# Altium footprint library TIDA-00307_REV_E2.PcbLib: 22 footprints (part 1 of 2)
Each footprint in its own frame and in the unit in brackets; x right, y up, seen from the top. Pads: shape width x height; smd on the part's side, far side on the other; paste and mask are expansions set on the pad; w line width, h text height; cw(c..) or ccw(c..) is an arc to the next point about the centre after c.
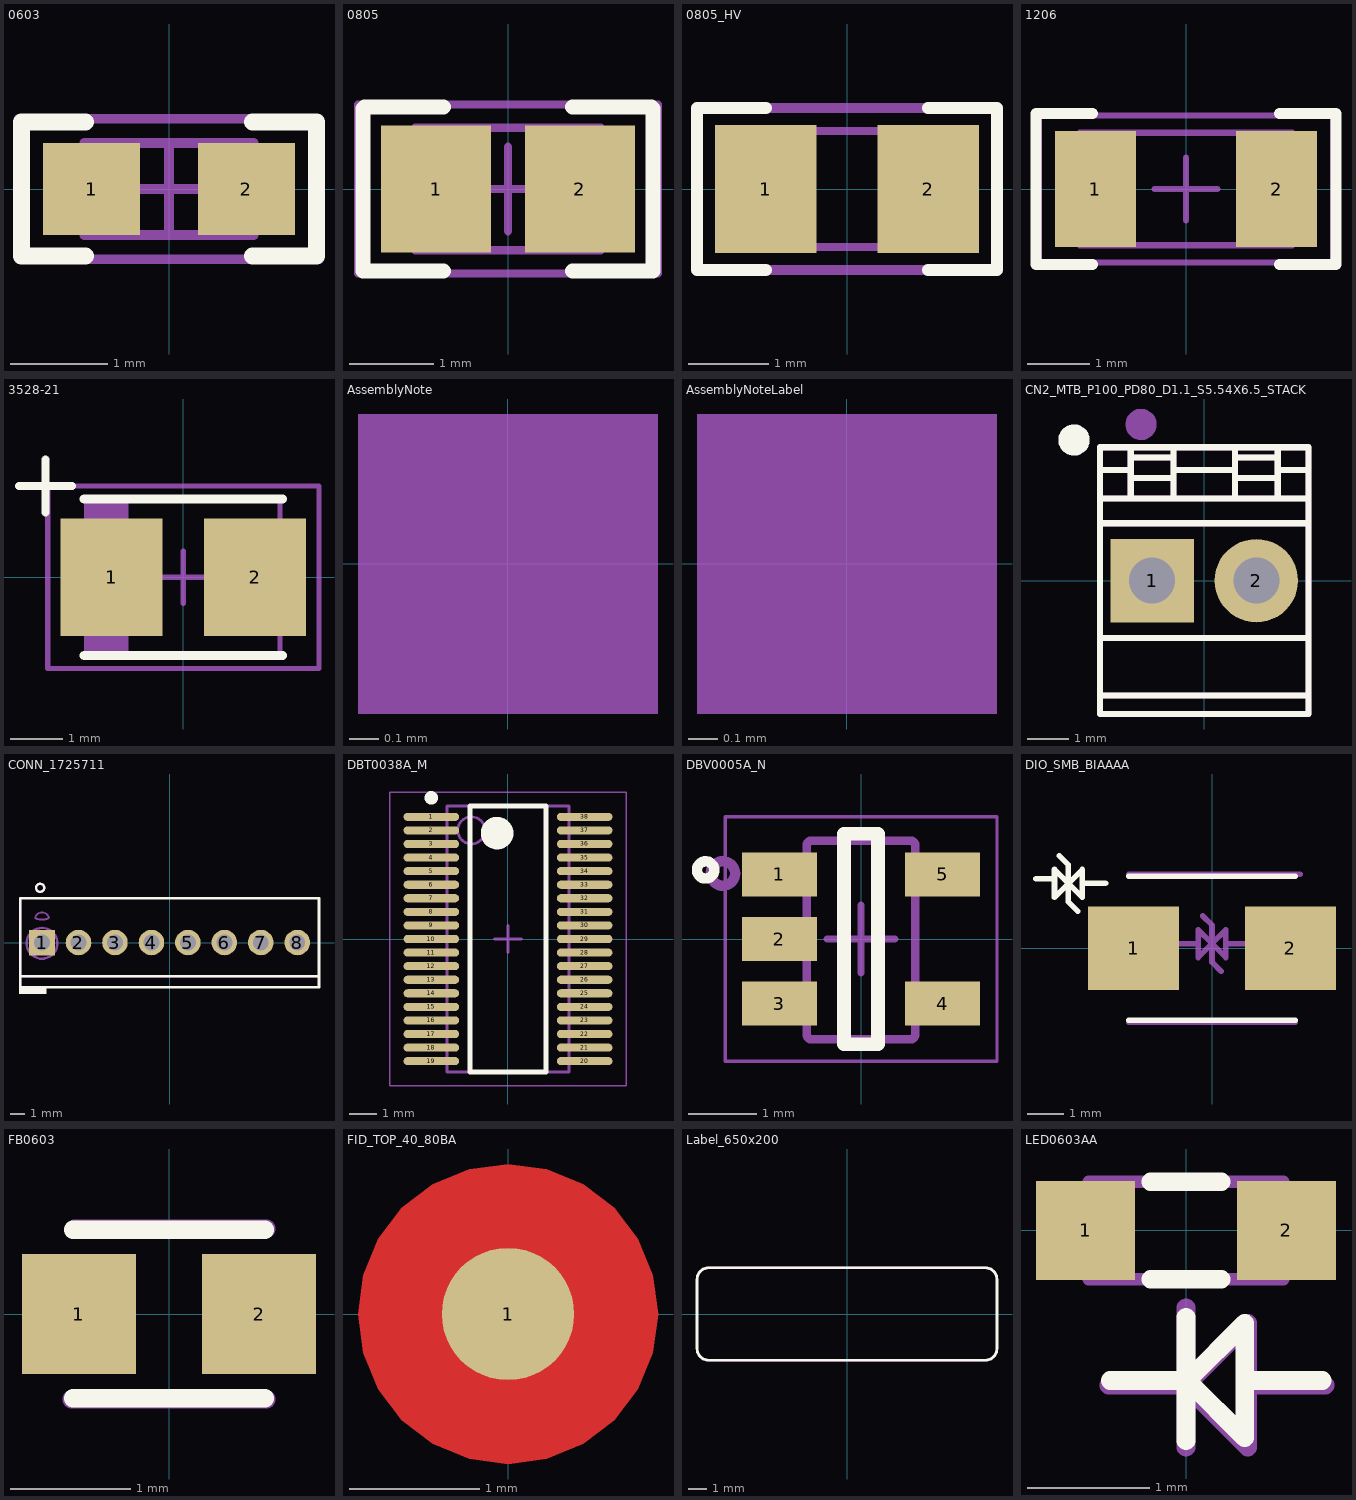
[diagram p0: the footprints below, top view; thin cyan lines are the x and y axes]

## 0603 [mm] "0603 from SM-752 data"
height 0.85
pads (2):
  rect 1x0.95 smd: 1(-0.8,0) 2(0.8,0)
Top Overlay:
  lines w0.178: -0.864,-0.691 -1.524,-0.691 -1.524,0.693 -0.864,0.693 ; 0.864,-0.691 1.524,-0.691 1.524,0.693 0.864,0.693
Mechanical 5:
  lines w0.1: -1.55,-0.725 1.55,-0.725 1.55,0.725 -1.55,0.725 -1.55,-0.725
  text ".Designator" at -0.991,-0.432 h0.76
Mechanical 13:
  lines w0.1: -0.55,-0.475 -0.55,0.475 ; 0.55,-0.475 0.55,0.475 ; -0.875,-0.475 -0.875,0.475 0.875,0.475 0.875,-0.475 -0.875,-0.475
Mechanical 15:
  lines w0.1: -0.475,0 0.475,0 ; 0,-0.475 0,0.475 ; -1.55,-0.725 -1.55,0.725 1.55,0.725 1.55,-0.725 -1.55,-0.725
3D body: height 0.85, standoff 0, extent 0.551,-0.474 0.874,0.474
3D body: height 0.85, standoff 0, extent -0.549,-0.474 0.549,0.474
3D body: height 0.85, standoff 0, extent -0.874,-0.474 -0.551,0.474

## 0805 [mm] "0805 from SM-752 data"
height 1.1
pads (2):
  rect 1.3x1.5 smd: 1(-0.85,0) 2(0.85,0)
Top Overlay:
  lines w0.178: -0.762,-0.968 -1.717,-0.968 -1.717,0.95 -1.699,0.968 -0.762,0.968 ; 0.762,-0.968 1.717,-0.968 1.717,0.95 1.699,0.968 0.762,0.968
Mechanical 5:
  lines w0.1: -1.775,-1 -1.775,1 1.775,1 1.775,-1 -1.775,-1
  text ".Designator" at 1.092,0.432 h0.81
Mechanical 13:
  lines w0.1: -0.65,-0.725 -0.65,0.725 ; 0.65,-0.725 0.65,0.725 ; -1.1,-0.725 -1.1,0.725 1.1,0.725 1.1,-0.725 -1.1,-0.725
Mechanical 15:
  lines w0.1: -0.5,0 0.5,0 ; 0,-0.5 0,0.5 ; -1.775,-1 -1.775,1 1.775,1 1.775,-1 -1.775,-1
3D body: height 1.1, standoff 0, extent 0.651,-0.724 1.099,0.724
3D body: height 1.1, standoff 0, extent -0.649,-0.724 0.649,0.724
3D body: height 1.1, standoff 0, extent -1.099,-0.724 -0.651,0.724

## 0805_HV [mil] "0805 with 30mil clearance between pads"
height 43.31
pads (2):
  rect 50x63 smd: 1(-40,0) 2(40,0)
Top Overlay:
  lines w6: -40,-40 -74,-40 -74,0 -74,40 -40,40 ; 40,-40 74,-40 74,0 74,40 40,40
Mechanical 5:
  lines w5: -74,-40 -74,40 74,40 74,-40 -74,-40
  text ".Designator" at 42,16 h30
Mechanical 13:
  lines w3.94: -25.59,-28.54 -25.59,28.54 ; 25.59,-28.54 25.59,28.54 ; -43.31,-28.54 43.31,-28.54 43.31,28.54 -43.31,28.54 -43.31,-28.54
3D body: height 43.31, standoff 0, extent -43.29,-28.52 -25.61,28.52
3D body: height 43.31, standoff 0, extent -25.57,-28.52 25.57,28.52
3D body: height 43.31, standoff 0, extent 25.61,-28.52 43.29,28.52

## 1206 [mm] "1206 from SM-752 data"
height 1.35
pads (2):
  rect 1.3x1.85 smd: 1(-1.45,0) 2(1.45,0)
Top Overlay:
  lines w0.178: -1.5,-1.21 -2.4,-1.21 -2.4,1.21 -1.5,1.21 ; 1.5,-1.21 2.4,-1.21 2.4,1.21 1.5,1.21
Mechanical 5:
  lines w0.1: -1.7,-0.9 -1.7,0.9 1.7,0.9 1.7,-0.9 -1.7,-0.9
  text ".Designator" at -1.27,-0.356 h0.76
Mechanical 13:
  lines w0.1: -1.2,-0.9 -1.2,0.9 ; 1.2,-0.9 1.2,0.9 ; -1.7,-0.9 -1.7,0.9 1.7,0.9 1.7,-0.9 -1.7,-0.9
Mechanical 15:
  lines w0.1: -0.5,0 0.5,0 ; 0,-0.5 0,0.5 ; -2.35,-1.175 -2.35,1.175 2.35,1.175 2.35,-1.175 -2.35,-1.175
3D body: height 1.35, standoff 0, extent 1.201,-0.899 1.699,0.899
3D body: height 1.35, standoff 0, extent -1.199,-0.899 1.199,0.899
3D body: height 1.35, standoff 0, extent -1.699,-0.899 -1.201,0.899

## 3528-21 [mm] "Medium Density IPC, based on SM-782 section 8.4"
height 2.1
pads (2):
  rect 1.95x2.25 smd: 1(-1.375,0) 2(1.375,0)
Top Overlay:
  lines w0.152: -3.15,1.753 -2.134,1.753 ; -2.642,1.245 -2.642,2.261
  lines w0.178: -1.9,-1.5 1.9,-1.5 ; -1.9,1.5 1.9,1.5
Mechanical 5:
  rectangle: -1.85,-1.499 -1.1,1.501
  lines w0.1: -1.1,-1.5 -1.1,1.5 ; -1.85,-1.5 -1.85,1.5 1.85,1.5 1.85,-1.5 -1.85,-1.5
  text ".Designator" at -0.66,-0.381 h0.71
Mechanical 15:
  lines w0.1: -0.5,0 0.5,0 ; 0,-0.5 0,0.5 ; -2.6,-1.75 2.6,-1.75 2.6,1.75 -2.6,1.75 -2.6,-1.75
3D body: height 2.1, standoff 0, extent -1.85,-1.5 1.85,1.5
3D body: height 2.1, standoff 2.1, extent -1.849,-1.499 -1.101,1.499

## AssemblyNote [mm] "Assembly Note"
height 1.905
Mechanical 5:
  rectangle: -0.508,-0.508 0.508,0.508
  text ".Comment" at 1.143,-0.508 h0.76
  text ".Designator" at -4.191,-0.508 h0.76

## AssemblyNoteLabel [mm] "Assembly Note for PCB Labels"
height 1.905
Mechanical 5:
  rectangle: -0.508,-0.508 0.508,0.508
  text "Install label in silkscreened box after final wash.  Text shall be 8 pt font.  Text shall be per the Label Table in the PDF schematic." at 1.651,-0.457 h0.76
  text ".Designator" at -3.683,-0.457 h0.76

## CN2_MTB_P100_PD80_D1.1_S5.54X6.5_STACK [mil]
height 400
pads (2):
  rect 80x80 / inner round 80 / far side rect 80x80 hole 44: 1(-50,0)
  round 80 hole 44: 2(50,0)
Top Overlay:
  circle w10: c-125,135 r10
  circle w10: c-125,135 r5
  lines w6: -100,-110.24 100,-110.24 ; -100,-55.12 100,-55.12 ; -100,55.12 100,55.12 ; -100,78.74 100,78.74 ; -100,106.3 -70.87,106.3 ; -70.47,78.74 -70.47,127.95 ; -70.47,98.43 -31.5,98.43 ; -70.47,118.11 -31.5,118.11 ; -29.53,78.74 -29.53,127.95 ; -27.56,106.3 27.56,106.3 ; 29.53,78.74 29.53,127.95 ; 31.5,98.43 66.93,98.43 ; 31.5,118.11 66.93,118.11 ; 70.47,78.74 70.47,127.95 ; 70.87,106.3 100,106.3 ; -100,-127.95 100,-127.95 100,127.95 -100,127.95 -100,-127.95
Mechanical 5:
  circle w10: c-60.63,149.95 r10
  circle w10: c-60.63,149.95 r5
  lines w6: -100,-110.24 100,-110.24 ; -100,-55.12 100,-55.12 ; -100,55.12 100,55.12 ; -100,78.74 100,78.74 ; -100,106.3 -70.87,106.3 ; -70.47,78.74 -70.47,127.95 ; -70.47,98.43 -31.5,98.43 ; -70.47,118.11 -31.5,118.11 ; -29.53,78.74 -29.53,127.95 ; -27.56,106.3 27.56,106.3 ; 29.53,78.74 29.53,127.95 ; 31.5,98.43 66.93,98.43 ; 31.5,118.11 66.93,118.11 ; 70.47,78.74 70.47,127.95 ; 70.87,106.3 100,106.3 ; -100,-127.95 100,-127.95 100,127.95 -100,127.95 -100,-127.95
  text ".designator" at 188.59,105.68 h40

## CONN_1725711 [mm] "Phoenix Contact"
height 13.8
pads (8):
  rect 1.78x1.78 hole 1.1: 1(-8.89,0)
  round 1.78 hole 1.1: 2(-6.35,0) 3(-3.81,0) 4(-1.27,0) 5(1.27,0) 6(3.81,0) 7(6.35,0) 8(8.89,0)
Top Overlay:
  circle w0.152: c-9.017,3.81 r0.284
  rectangle: -10.493,-3.6 -8.589,-3.1
  lines w0.178: -10.39,-2.361 10.39,-2.361 ; -10.404,-3.1 -10.398,3.1 10.4,3.1 10.4,-3.1 -10.404,-3.1
Mechanical 5:
  circle w0.152: c-9.017,3.81 r0.284
  lines w0.127: -10.39,-2.361 10.39,-2.361 ; -10.39,-2.361 -10.39,-1.51 -10.39,-1.22 -10.39,1.132 -10.39,1.417 -10.39,3.1 10.39,3.1 10.39,1.417 10.39,1.132 10.39,-1.22 10.39,-1.51 10.39,-2.361 ; -10.39,-2.361 -10.39,-2.8 -10.39,-3.1 10.39,-3.1 10.39,-2.8 10.39,-2.361 ; -9.788,-0.594 ccw(c-8.89,-0.05) -9.434,-0.948 ; -9.788,-0.594 cw(c-8.89,-0.05) -8.89,1 cw(c-8.89,-0.05) -8.346,0.848 ; -9.788,-0.594 -9.4,-0.206 -8.89,0.304 -8.684,0.51 -8.346,0.848 ; -9.434,-0.948 ccw(c-8.89,-0.05) -8.89,-1.1 ccw(c-8.89,-0.05) -7.992,0.494 ; -9.434,-0.948 -9.021,-0.534 -8.89,-0.403 -8.356,0.131 -7.992,0.494 ; -8.346,0.848 cw(c-8.89,-0.05) -7.992,0.494 ; -9.365,1.741 -9.365,1.748 -9.365,1.755 -9.363,1.763 cw(c-8.89,1.6) -8.89,2.1 cw(c-8.89,1.6) -8.417,1.763 -8.415,1.751 -8.415,1.744 -8.416,1.737 -8.418,1.729 -8.421,1.722 -8.426,1.715 -8.432,1.708 -8.439,1.701 -8.447,1.694 -8.456,1.687 -8.466,1.68 -8.477,1.674 -8.49,1.668 -8.503,1.662 -8.517,1.656 -8.533,1.65 -8.549,1.645 -8.566,1.639 -8.584,1.635 -8.602,1.63 -8.621,1.626 -8.641,1.622 -8.662,1.618 -8.683,1.615 -8.705,1.612 -8.727,1.609 -8.749,1.607 -8.772,1.605 -8.795,1.603 -8.819,1.602 -8.842,1.601 -8.866,1.6 -8.89,1.6 -8.926,1.6 -8.95,1.601 -8.973,1.602 -8.997,1.604 -9.02,1.606 -9.042,1.608 -9.065,1.61 -9.087,1.613 -9.108,1.616 -9.129,1.62 -9.149,1.624 -9.169,1.628 -9.188,1.632 -9.206,1.637 -9.223,1.642 -9.24,1.647 -9.255,1.653 -9.27,1.659 -9.284,1.665 -9.297,1.671 -9.309,1.677 -9.319,1.684 -9.329,1.691 -9.338,1.697 -9.345,1.704 -9.351,1.711 -9.357,1.719 -9.361,1.726 -9.363,1.733 -9.365,1.741 ; -8.89,-1.15 ccw(c-8.89,-0.05) -8.89,1.05 ccw(c-8.89,-0.05) -8.89,-1.15
  text ".Designator" at 10.922,3.658 h1.02
3D body: height 8.52, standoff -3.48, extent -10.39,-3.1 10.39,3.1

## DBT0038A_M [mm] "TSSOP, 38-Leads, Body 9.7x4.4mm, Pitch 0.5mm, IPC Low Density"
height 1.2
pads (38):
  oval 2.05x0.3 smd: 1(-2.825,4.5) 2(-2.825,4) 3(-2.825,3.5) 4(-2.825,3) 5(-2.825,2.5) 6(-2.825,2) 7(-2.825,1.5) 8(-2.825,1) 9(-2.825,0.5) 10(-2.825,0) 11(-2.825,-0.5) 12(-2.825,-1) 13(-2.825,-1.5) 14(-2.825,-2) 15(-2.825,-2.5) 16(-2.825,-3) 17(-2.825,-3.5) 18(-2.825,-4) 19(-2.825,-4.5) 20(2.825,-4.5) 21(2.825,-4) 22(2.825,-3.5) 23(2.825,-3) 24(2.825,-2.5) 25(2.825,-2) 26(2.825,-1.5) 27(2.825,-1) 28(2.825,-0.5) 29(2.825,0) 30(2.825,0.5) 31(2.825,1) 32(2.825,1.5) 33(2.825,2) 34(2.825,2.5) 35(2.825,3) 36(2.825,3.5) 37(2.825,4) 38(2.825,4.5)
Top Overlay:
  circle w0.25: c-2.825,5.2 r0.125
  circle w0.6: c-0.4,3.9 r0.3
  lines w0.2: -1.4,-4.9 -1.4,4.9 1.4,4.9 1.4,-4.9 -1.4,-4.9
Mechanical 5:
  circle w0.1: c-1.35,4 r0.5
  lines w0.1: -2.25,-4.9 -2.25,4.9 2.25,4.9 2.25,-4.9 -2.25,-4.9
  text ".Designator" at 0.533,-0.847 h1.02
Mechanical 15:
  lines w0.05: -4.35,-5.4 -4.35,5.4 4.35,5.4 4.35,-5.4 -4.35,-5.4
  lines w0.1: -0.5,0 0.5,0 ; 0,-0.5 0,0.5
3D body: height 1.2, standoff 0.05, extent -2.25,-4.9 2.25,4.9

## DBV0005A_N [mm] "SOT23, 5-Leads, Body 2.9x1.6mm, Pitch 0.95mm, Lead Span 2.8mm, IPC Medium Density"
height 1.45
pads (5):
  rect 1.1x0.65 smd: 1(-1.2,0.95) 2(-1.2,0) 3(-1.2,-0.95) 4(1.2,-0.95) 5(1.2,0.95)
Top Overlay:
  circle w0.152: c-2.286,1.016 r0.127
  lines w0.2: -0.25,-1.55 -0.25,1.55 0.25,1.55 0.25,-1.55 -0.25,-1.55
Mechanical 5:
  circle w0.152: c-2.032,0.963 r0.18
  lines w0.127: -0.801,1.371 cw(c-0.725,1.37) -0.725,1.446 ; -0.801,1.37 -0.801,1.371 ; -0.801,1.37 -0.801,-1.399 -0.801,-1.4 ccw(c-0.725,-1.399) -0.725,-1.475 ; -0.725,-1.475 0.723,-1.475 0.724,-1.475 ccw(c0.723,-1.399) 0.799,-1.4 0.799,-1.399 0.799,1.37 ; -0.725,-1.475 -0.725,-1.475 ; -0.725,1.446 -0.725,1.446 ; -0.725,1.446 0.723,1.446 0.724,1.446 cw(c0.723,1.37) 0.799,1.371 ; 0.799,1.37 0.799,1.371 ; -1.423,-1.167 -1.423,-0.767 -1.199,-0.767 -1.105,-0.767 -1.088,-0.767 -0.835,-0.767 -0.801,-0.767 -0.801,-1.167 -0.835,-1.167 -1.088,-1.167 -1.105,-1.167 -1.199,-1.167 -1.423,-1.167 ; -1.423,-0.215 -1.423,0.186 -1.199,0.186 -1.105,0.186 -1.088,0.186 -0.835,0.186 -0.801,0.186 -0.801,-0.215 -0.835,-0.215 -1.088,-0.215 -1.105,-0.215 -1.199,-0.215 -1.423,-0.215 ; -1.423,0.738 -1.423,1.138 -1.199,1.138 -1.105,1.138 -1.088,1.138 -0.835,1.138 -0.801,1.138 -0.801,0.738 -0.835,0.738 -1.088,0.738 -1.105,0.738 -1.199,0.738 -1.423,0.738 ; 0.799,-1.167 0.834,-1.167 1.087,-1.167 1.103,-1.167 1.198,-1.167 1.422,-1.167 1.422,-0.767 1.198,-0.767 1.103,-0.767 1.087,-0.767 0.834,-0.767 0.799,-0.767 0.799,-1.167 ; 0.799,0.738 0.834,0.738 1.087,0.738 1.103,0.738 1.198,0.738 1.422,0.738 1.422,1.138 1.198,1.138 1.103,1.138 1.087,1.138 0.834,1.138 0.799,1.138 0.799,0.738
  text ".Designator" at 0.356,-0.686 h0.76
Mechanical 15:
  lines w0.05: -2,-1.8 2,-1.8 2,1.8 -2,1.8 -2,-1.8
  lines w0.1: -0.5,0 0.5,0 ; 0,-0.5 0,0.5
3D body: height 1.08, standoff -0.01, extent -1.422,-1.461 1.422,1.46

## DIO_SMB_BIAAAA [mm]
height 2.28
pads (2):
  rect 2.5x2.3 smd: 1(-2.15,0) 2(2.15,0)
Top Overlay:
  lines w0.152: -4.826,1.905 -4.318,1.905 ; -4.191,2.54 -3.937,2.286 -3.937,1.27 -3.683,1.016 ; -3.556,1.778 -2.921,1.778 ; -2.285,-1.97 2.285,-1.97 ; -2.285,1.97 2.285,1.97 ; -3.937,1.778 -4.318,1.397 -4.318,2.159 -3.937,1.778 ; -3.937,1.778 -3.556,2.159 -3.556,1.397 -3.937,1.778
Mechanical 5:
  lines w0.152: -2.286,-2.032 2.286,-2.032 ; -2.286,2.032 2.413,2.032 ; -0.889,0.127 -0.381,0.127 ; -0.254,0.889 0,0.635 0,-0.381 0.254,-0.635 ; 0.381,0.127 1.016,0.127 ; -0.381,-0.254 0,0.127 ; -0.381,-0.254 -0.381,0.508 ; -0.381,-0.254 -0.381,0.508 ; -0.381,0.508 0,0.127 ; 0,0.127 0.381,0.508 0.381,-0.254 0,0.127
  text ".designator" at -3.404,-0.508 h1.02
Mechanical 15:
  lines w0.025: -2.285,-1.97 2.285,-1.97 ; -2.285,1.97 2.285,1.97

## FB0603 [mm]
height 0.95
pads (2):
  rect 0.95x1 smd: 1(-0.75,0) 2(0.75,0)
Top Overlay:
  lines w0.152: -0.8,-0.703 0.8,-0.703 ; -0.8,0.703 0.8,0.703
Mechanical 5:
  lines w0.152: -0.813,-0.711 0.813,-0.711 ; -0.787,0.711 0.813,0.711
  text ".Designator" at 0.94,0.33 h0.76
Mechanical 15:
  lines w0.025: -0.8,-0.4 -0.8,0.4 ; 0.8,-0.4 0.8,0.4
  lines w0.1: -0.8,-0.4 -0.8,0.4

## FID_TOP_40_80BA [mil]
pads (1):
  round 40 smd mask+20: 1(0,0)
Top Layer:
  region: 45.39,0 43.84,11.75 39.31,22.69 32.09,32.09 22.69,39.31 11.75,43.84 0,45.39 -11.75,43.84 -22.69,39.31 -32.09,32.09 -39.31,22.69 -43.84,11.75 -45.39,0 -43.84,-11.75 -39.31,-22.69 -32.09,-32.09 -22.69,-39.31 -11.75,-43.84 0,-45.39 11.75,-43.84 22.69,-39.31 32.09,-32.09 39.31,-22.69 43.84,-11.75

## Label_650x200 [mm] "Thermal Transfer Label"
height 0.025
Top Overlay:
  lines w0.152: -8.255,-1.905 ccw(c-7.62,-1.905) -7.62,-2.54 7.62,-2.54 ccw(c7.62,-1.905) 8.255,-1.905 8.255,1.905 ccw(c7.62,1.905) 7.62,2.54 -7.62,2.54 ccw(c-7.62,1.905) -8.255,1.905 -8.255,-1.905
Mechanical 5:
  lines w0.127: -8.255,-1.905 ccw(c-7.62,-1.905) -7.62,-2.54 7.62,-2.54 ccw(c7.62,-1.905) 8.255,-1.905 8.255,1.905 ccw(c7.62,1.905) 7.62,2.54 -7.62,2.54 ccw(c-7.62,1.905) -8.255,1.905 -8.255,-1.905
  text ".Designator" at -1.524,-0.508 h0.76
3D body: height 0.03, standoff 0, extent -8.268,-2.553 8.268,2.553

## LED0603AA [mil]
height 35.43
pads (2):
  rect 32x32 smd: 1(-32.48,0) 2(32.48,0)
Top Overlay:
  lines w6: -24.5,-48.5 0.5,-48.5 ; -11.42,-15.75 11.42,-15.75 ; -11.42,15.75 11.42,15.75 ; 0,-68 0,-28 ; 19,-48.5 44,-48.5 ; 0.5,-48.5 19,-30 19,-67 0.5,-48.5
Mechanical 5:
  lines w4: -31.5,-15.75 31.5,-15.75 31.5,15.75 -31.5,15.75 -31.5,-15.75
  lines w6: -25,-50 0,-50 ; 0,-70 0,-25 ; 20,-50 45,-50 ; 0,-50 20,-30 20,-70 0,-50
  text ".Designator" at -20,-109 h30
